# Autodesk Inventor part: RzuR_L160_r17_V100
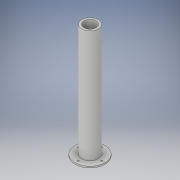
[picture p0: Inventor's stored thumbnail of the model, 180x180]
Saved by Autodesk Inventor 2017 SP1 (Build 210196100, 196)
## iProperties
Part Number: RzuR_L160_r17_V100
Material: Generisch
Document SubType Name: Modeling
Designer: haesner
Density: 1 g/cm^3
Appearance: Vorgabe
Part Number: RzuR_L160_r17_V100_3D-Druck
Author: haesner
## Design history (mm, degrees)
sketch "Skizze1"
  geometry: C1 r 8.5 at (0, 0); C2 r 11.5 at (0, 0); 1 further point
  constraints: 2 centre point, 2 coincident
  dimensions: "d0" = 17 diameter of C1; "d1" = 23 diameter of C2
extrude "Extrusion1" new body sketch "Skizze1" distance "d2" = 160; taper "d3" = 0 deg
sketch "Skizze2"
  geometry: C1 r 21 at (0, 0); C2 r 11.5 at (0, 0) reference; 1 further point
  constraints: 1 centre point, 1 coincident
  dimensions: "d4" = 42 diameter of C1
extrude "Extrusion2" join sketch "Skizze2" distance "d5" = 2; taper "d6" = 0 deg
sketch "Skizze3"
  geometry: L1 (16.5, 0)-(0, 16.5); L2 (0, 16.5)-(-16.5, 0); L3 (-16.5, 0)-(0, -16.5); L4 (0, -16.5)-(16.5, 0); L5 (0, -29.4)-(0, 29.4) reference; L6 (29.4, 0)-(-29.4, 0) reference; 1 further point
  constraints: 8 end point, 3 point on line, 2 parallel, 2 perpendicular
  dimensions: "d7" = 16.5 distance from line of L5 L1.start
hole "Bohrung1" sketch "Skizze3" at (16.5, 0), (0, 16.5), (-16.5, 0), (0, -16.5) diameter "d8" = 2.3; stored, may be unused: countersink angle "d12" = 90 deg, drill point angle "d14" = 118 deg; dims "d9" = 6, "d10" = 4, "d11" = 2, "d13" = 8
node "Volumenkörper1"
